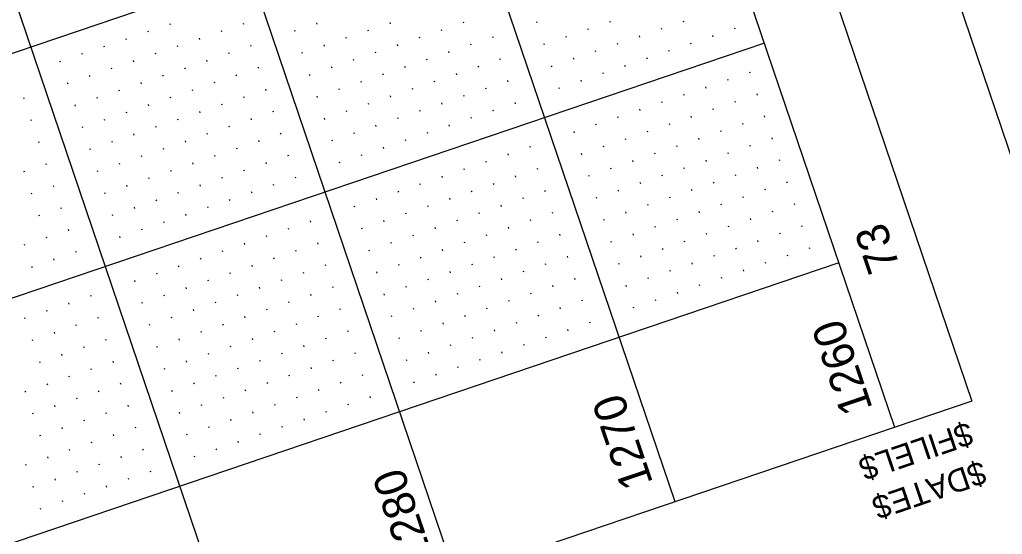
# Model space of a CAD drawing. Extents: x 2150800 to 2152547, y 141860 to 143950.
# Drawn here: x 2152172.8 to 2152384.7, y 142359.9 to 142470.9 of the extents above; entities that cross this region are included whole.
import ezdxf

# ---------------------------------------------------------------- set-up
doc = ezdxf.new("R2010")
doc.units = 0
for name, color, linetype in [('SHT_Plan_Profile_Sheet_Elev_Txt', 7, 'Continuous'), ('SHT_Plan_Profile_Sheet_Sta_Txt', 7, 'Continuous'), ('SHT_Plot_Shape_Half', 7, 'Continuous'), ('SHT_Plot_Stamp', 7, 'Continuous'), ('SHT_Profile_Grid_Major', 7, 'Continuous'), ('SHT_Profile_Grid_Minor', 7, 'Continuous'), ('SHT_Sheet_Border', 7, 'Continuous')]:
    doc.layers.add(name, color=color, linetype=linetype)

msp = doc.modelspace()

# ---------------------------------------------------------------- linework, layer by layer
at = {"layer": 'SHT_Plot_Shape_Half'}
msp.add_lwpolyline([(2151391.39, 141950.92), (2150845.24, 143560.8), (2151886.93, 143914.19), (2152433.08, 142304.31)], close=True, dxfattribs=at)
at = {"layer": 'SHT_Profile_Grid_Major'}
for p, q in [((2152314.16, 142366.92), (2151808.17, 143858.43)), ((2152266.81, 142350.86), (2151760.82, 143842.37)), ((2152219.46, 142334.8), (2151713.47, 143826.31)), ((2152317.33, 142513.2), (2151867.44, 142360.57)), ((2152333.4, 142465.85), (2151883.5, 142313.22))]:
    msp.add_line(p, q, dxfattribs=at)
at = {"layer": 'SHT_Profile_Grid_Minor'}
for p, q in [((2152205.34, 142469.79), (2152205.26, 142470.03)), ((2152221.15, 142469.88), (2152221.07, 142470.11)), ((2152236.96, 142469.96), (2152236.88, 142470.2)), ((2152252.78, 142470.04), (2152252.7, 142470.28)), ((2152263.85, 142468.52), (2152263.77, 142468.76)), ((2152268.59, 142470.13), (2152268.51, 142470.36)), ((2152284.4, 142470.21), (2152284.32, 142470.45)), ((2152295.47, 142468.69), (2152295.39, 142468.93)), ((2152300.21, 142470.3), (2152300.13, 142470.53)), ((2152311.29, 142468.77), (2152311.21, 142469.01)), ((2152316.02, 142470.38), (2152315.94, 142470.62)), ((2152327.1, 142468.86), (2152327.02, 142469.09)), ((2152195.87, 142466.58), (2152195.79, 142466.82)), ((2152200.61, 142468.19), (2152200.53, 142468.42)), ((2152211.68, 142466.66), (2152211.6, 142466.9)), ((2152216.42, 142468.27), (2152216.34, 142468.51)), ((2152232.23, 142468.35), (2152232.15, 142468.59)), ((2152243.31, 142466.83), (2152243.23, 142467.07)), ((2152248.04, 142468.44), (2152247.96, 142468.67)), ((2152259.12, 142466.92), (2152259.04, 142467.15)), ((2152274.93, 142467), (2152274.85, 142467.24)), ((2152290.74, 142467.08), (2152290.66, 142467.32)), ((2152306.55, 142467.17), (2152306.47, 142467.4)), ((2152322.36, 142467.25), (2152322.28, 142467.49)), ((2152191.14, 142464.97), (2152191.06, 142465.21)), ((2152206.95, 142465.06), (2152206.87, 142465.29)), ((2152222.76, 142465.14), (2152222.68, 142465.38)), ((2152238.57, 142465.22), (2152238.49, 142465.46)), ((2152254.38, 142465.31), (2152254.3, 142465.55)), ((2152270.19, 142465.39), (2152270.11, 142465.63)), ((2152286, 142465.48), (2152285.92, 142465.71)), ((2152301.82, 142465.56), (2152301.74, 142465.8)), ((2152317.63, 142465.64), (2152317.55, 142465.88)), ((2152186.4, 142463.37), (2152186.32, 142463.6)), ((2152202.21, 142463.45), (2152202.13, 142463.69)), ((2152218.03, 142463.53), (2152217.94, 142463.77)), ((2152233.84, 142463.62), (2152233.76, 142463.86)), ((2152249.65, 142463.7), (2152249.57, 142463.94)), ((2152260.72, 142462.18), (2152260.64, 142462.42)), ((2152265.46, 142463.79), (2152265.38, 142464.02)), ((2152276.53, 142462.26), (2152276.45, 142462.5)), ((2152292.35, 142462.35), (2152292.27, 142462.58)), ((2152297.08, 142463.95), (2152297, 142464.19)), ((2152308.16, 142462.43), (2152308.08, 142462.67)), ((2152312.89, 142464.04), (2152312.81, 142464.28)), ((2152181.67, 142461.76), (2152181.59, 142462)), ((2152192.74, 142460.24), (2152192.66, 142460.47)), ((2152197.48, 142461.84), (2152197.4, 142462.08)), ((2152208.56, 142460.32), (2152208.47, 142460.56)), ((2152213.29, 142461.93), (2152213.21, 142462.16)), ((2152224.37, 142460.41), (2152224.29, 142460.64)), ((2152240.18, 142460.49), (2152240.1, 142460.73)), ((2152244.91, 142462.1), (2152244.83, 142462.33)), ((2152255.99, 142460.57), (2152255.91, 142460.81)), ((2152271.8, 142460.66), (2152271.72, 142460.89)), ((2152287.61, 142460.74), (2152287.53, 142460.98)), ((2152303.42, 142460.83), (2152303.34, 142461.06)), ((2152188.01, 142458.63), (2152187.93, 142458.87)), ((2152203.82, 142458.72), (2152203.74, 142458.95)), ((2152219.63, 142458.8), (2152219.55, 142459.04)), ((2152235.44, 142458.88), (2152235.36, 142459.12)), ((2152251.25, 142458.97), (2152251.17, 142459.2)), ((2152267.06, 142459.05), (2152266.98, 142459.29)), ((2152298.69, 142459.22), (2152298.61, 142459.46)), ((2152330.31, 142459.39), (2152330.23, 142459.62)), ((2152183.27, 142457.03), (2152183.19, 142457.26)), ((2152199.09, 142457.11), (2152199, 142457.35)), ((2152214.9, 142457.19), (2152214.82, 142457.43)), ((2152246.52, 142457.36), (2152246.44, 142457.6)), ((2152257.59, 142455.84), (2152257.51, 142456.08)), ((2152262.33, 142457.45), (2152262.25, 142457.68)), ((2152273.41, 142455.92), (2152273.33, 142456.16)), ((2152278.14, 142457.53), (2152278.06, 142457.77)), ((2152289.22, 142456.01), (2152289.14, 142456.24)), ((2152293.95, 142457.61), (2152293.87, 142457.85)), ((2152320.84, 142456.17), (2152320.76, 142456.41)), ((2152325.57, 142457.78), (2152325.49, 142458.02)), ((2152173.8, 142453.81), (2152173.72, 142454.05)), ((2152189.62, 142453.9), (2152189.54, 142454.13)), ((2152194.35, 142455.5), (2152194.27, 142455.74)), ((2152205.43, 142453.98), (2152205.35, 142454.22)), ((2152210.16, 142455.59), (2152210.08, 142455.82)), ((2152221.24, 142454.06), (2152221.16, 142454.3)), ((2152225.97, 142455.67), (2152225.89, 142455.91)), ((2152237.05, 142454.15), (2152236.97, 142454.39)), ((2152241.78, 142455.75), (2152241.7, 142455.99)), ((2152252.86, 142454.23), (2152252.78, 142454.47)), ((2152268.67, 142454.32), (2152268.59, 142454.55)), ((2152316.1, 142454.57), (2152316.02, 142454.81)), ((2152331.92, 142454.65), (2152331.84, 142454.89)), ((2152184.88, 142452.29), (2152184.8, 142452.53)), ((2152200.69, 142452.37), (2152200.61, 142452.61)), ((2152216.5, 142452.46), (2152216.42, 142452.69)), ((2152248.13, 142452.63), (2152248.04, 142452.86)), ((2152263.94, 142452.71), (2152263.86, 142452.95)), ((2152279.75, 142452.79), (2152279.67, 142453.03)), ((2152311.37, 142452.96), (2152311.29, 142453.2)), ((2152327.18, 142453.05), (2152327.1, 142453.28)), ((2152195.96, 142450.77), (2152195.88, 142451)), ((2152211.77, 142450.85), (2152211.69, 142451.09)), ((2152227.58, 142450.94), (2152227.5, 142451.17)), ((2152243.39, 142451.02), (2152243.31, 142451.26)), ((2152254.47, 142449.5), (2152254.39, 142449.73)), ((2152259.2, 142451.1), (2152259.12, 142451.34)), ((2152270.28, 142449.58), (2152270.2, 142449.82)), ((2152275.01, 142451.19), (2152274.93, 142451.42)), ((2152301.9, 142449.75), (2152301.82, 142449.99)), ((2152306.63, 142451.36), (2152306.55, 142451.59)), ((2152317.71, 142449.83), (2152317.63, 142450.07)), ((2152322.45, 142451.44), (2152322.37, 142451.68)), ((2152333.52, 142449.92), (2152333.44, 142450.15)), ((2152175.41, 142449.08), (2152175.33, 142449.31)), ((2152186.49, 142447.56), (2152186.41, 142447.79)), ((2152191.22, 142449.16), (2152191.14, 142449.4)), ((2152202.3, 142447.64), (2152202.22, 142447.88)), ((2152207.03, 142449.25), (2152206.95, 142449.48)), ((2152218.11, 142447.72), (2152218.03, 142447.96)), ((2152222.84, 142449.33), (2152222.76, 142449.57)), ((2152238.66, 142449.41), (2152238.57, 142449.65)), ((2152249.73, 142447.89), (2152249.65, 142448.13)), ((2152265.54, 142447.98), (2152265.46, 142448.21)), ((2152297.16, 142448.14), (2152297.08, 142448.38)), ((2152312.98, 142448.23), (2152312.9, 142448.46)), ((2152328.79, 142448.31), (2152328.71, 142448.55)), ((2152197.56, 142446.03), (2152197.48, 142446.27)), ((2152213.37, 142446.12), (2152213.29, 142446.35)), ((2152229.19, 142446.2), (2152229.1, 142446.44)), ((2152245, 142446.28), (2152244.92, 142446.52)), ((2152260.81, 142446.37), (2152260.73, 142446.61)), ((2152292.43, 142446.54), (2152292.35, 142446.77)), ((2152308.24, 142446.62), (2152308.16, 142446.86)), ((2152324.05, 142446.7), (2152323.97, 142446.94)), ((2152177.02, 142444.34), (2152176.94, 142444.58)), ((2152192.83, 142444.43), (2152192.75, 142444.66)), ((2152208.64, 142444.51), (2152208.56, 142444.75)), ((2152224.45, 142444.59), (2152224.37, 142444.83)), ((2152240.26, 142444.68), (2152240.18, 142444.92)), ((2152251.34, 142443.16), (2152251.26, 142443.39)), ((2152256.07, 142444.76), (2152255.99, 142445)), ((2152282.96, 142443.32), (2152282.88, 142443.56)), ((2152298.77, 142443.41), (2152298.69, 142443.65)), ((2152303.51, 142445.01), (2152303.43, 142445.25)), ((2152314.58, 142443.49), (2152314.5, 142443.73)), ((2152319.32, 142445.1), (2152319.24, 142445.34)), ((2152330.39, 142443.58), (2152330.31, 142443.81)), ((2152335.13, 142445.18), (2152335.05, 142445.42)), ((2152188.09, 142442.82), (2152188.01, 142443.06)), ((2152199.17, 142441.3), (2152199.09, 142441.53)), ((2152203.9, 142442.9), (2152203.82, 142443.14)), ((2152214.98, 142441.38), (2152214.9, 142441.62)), ((2152219.72, 142442.99), (2152219.64, 142443.23)), ((2152230.79, 142441.47), (2152230.71, 142441.7)), ((2152246.6, 142441.55), (2152246.52, 142441.79)), ((2152278.23, 142441.72), (2152278.14, 142441.95)), ((2152294.04, 142441.8), (2152293.96, 142442.04)), ((2152309.85, 142441.89), (2152309.77, 142442.12)), ((2152325.66, 142441.97), (2152325.58, 142442.21)), ((2152178.62, 142439.61), (2152178.54, 142439.84)), ((2152194.43, 142439.69), (2152194.35, 142439.93)), ((2152210.25, 142439.78), (2152210.17, 142440.01)), ((2152226.06, 142439.86), (2152225.98, 142440.1)), ((2152241.87, 142439.94), (2152241.79, 142440.18)), ((2152273.49, 142440.11), (2152273.41, 142440.35)), ((2152305.11, 142440.28), (2152305.03, 142440.52)), ((2152320.92, 142440.36), (2152320.84, 142440.6)), ((2152332, 142438.84), (2152331.92, 142439.08)), ((2152336.73, 142440.45), (2152336.65, 142440.68)), ((2152173.89, 142438), (2152173.81, 142438.24)), ((2152189.7, 142438.09), (2152189.62, 142438.32)), ((2152205.51, 142438.17), (2152205.43, 142438.41)), ((2152221.32, 142438.25), (2152221.24, 142438.49)), ((2152232.4, 142436.73), (2152232.32, 142436.97)), ((2152264.02, 142436.9), (2152263.94, 142437.14)), ((2152268.76, 142438.51), (2152268.67, 142438.74)), ((2152279.83, 142436.98), (2152279.75, 142437.22)), ((2152284.57, 142438.59), (2152284.49, 142438.83)), ((2152295.64, 142437.07), (2152295.56, 142437.3)), ((2152300.38, 142438.67), (2152300.3, 142438.91)), ((2152311.45, 142437.15), (2152311.37, 142437.39)), ((2152316.19, 142438.76), (2152316.11, 142438.99)), ((2152327.26, 142437.24), (2152327.18, 142437.47)), ((2152180.23, 142434.87), (2152180.15, 142435.11)), ((2152196.04, 142434.96), (2152195.96, 142435.19)), ((2152200.78, 142436.56), (2152200.7, 142436.8)), ((2152211.85, 142435.04), (2152211.77, 142435.28)), ((2152216.59, 142436.65), (2152216.51, 142436.88)), ((2152227.66, 142435.12), (2152227.58, 142435.36)), ((2152259.29, 142435.29), (2152259.21, 142435.53)), ((2152275.1, 142435.38), (2152275.02, 142435.61)), ((2152306.72, 142435.54), (2152306.64, 142435.78)), ((2152322.53, 142435.63), (2152322.45, 142435.87)), ((2152338.34, 142435.71), (2152338.26, 142435.95)), ((2152175.49, 142433.27), (2152175.41, 142433.5)), ((2152191.31, 142433.35), (2152191.23, 142433.59)), ((2152207.12, 142433.43), (2152207.04, 142433.67)), ((2152222.93, 142433.52), (2152222.85, 142433.76)), ((2152254.55, 142433.69), (2152254.47, 142433.92)), ((2152270.36, 142433.77), (2152270.28, 142434.01)), ((2152286.17, 142433.85), (2152286.09, 142434.09)), ((2152301.98, 142433.94), (2152301.9, 142434.18)), ((2152317.8, 142434.02), (2152317.71, 142434.26)), ((2152328.87, 142432.5), (2152328.79, 142432.74)), ((2152333.61, 142434.11), (2152333.53, 142434.34)), ((2152202.38, 142431.83), (2152202.3, 142432.06)), ((2152218.19, 142431.91), (2152218.11, 142432.15)), ((2152245.08, 142430.47), (2152245, 142430.71)), ((2152249.82, 142432.08), (2152249.74, 142432.32)), ((2152260.89, 142430.56), (2152260.81, 142430.79)), ((2152265.63, 142432.16), (2152265.55, 142432.4)), ((2152276.7, 142430.64), (2152276.62, 142430.88)), ((2152281.44, 142432.25), (2152281.36, 142432.48)), ((2152297.25, 142432.33), (2152297.17, 142432.57)), ((2152308.33, 142430.81), (2152308.24, 142431.05)), ((2152313.06, 142432.42), (2152312.98, 142432.65)), ((2152324.14, 142430.89), (2152324.06, 142431.13)), ((2152339.95, 142430.98), (2152339.87, 142431.21)), ((2152177.1, 142428.53), (2152177.02, 142428.77)), ((2152181.84, 142430.14), (2152181.76, 142430.37)), ((2152192.91, 142428.62), (2152192.83, 142428.85)), ((2152197.65, 142430.22), (2152197.57, 142430.46)), ((2152208.72, 142428.7), (2152208.64, 142428.94)), ((2152213.46, 142430.31), (2152213.38, 142430.54)), ((2152256.16, 142428.95), (2152256.08, 142429.19)), ((2152271.97, 142429.04), (2152271.89, 142429.27)), ((2152287.78, 142429.12), (2152287.7, 142429.36)), ((2152303.59, 142429.2), (2152303.51, 142429.44)), ((2152319.4, 142429.29), (2152319.32, 142429.52)), ((2152335.21, 142429.37), (2152335.13, 142429.61)), ((2152203.99, 142427.09), (2152203.91, 142427.33)), ((2152235.61, 142427.26), (2152235.53, 142427.5)), ((2152251.42, 142427.35), (2152251.34, 142427.58)), ((2152267.23, 142427.43), (2152267.15, 142427.67)), ((2152283.04, 142427.51), (2152282.96, 142427.75)), ((2152298.86, 142427.6), (2152298.77, 142427.83)), ((2152314.67, 142427.68), (2152314.59, 142427.92)), ((2152325.74, 142426.16), (2152325.66, 142426.4)), ((2152330.48, 142427.77), (2152330.4, 142428)), ((2152341.55, 142426.24), (2152341.47, 142426.48)), ((2152183.44, 142425.4), (2152183.36, 142425.64)), ((2152199.25, 142425.49), (2152199.17, 142425.72)), ((2152226.14, 142424.05), (2152226.06, 142424.29)), ((2152230.88, 142425.65), (2152230.8, 142425.89)), ((2152246.69, 142425.74), (2152246.61, 142425.98)), ((2152257.76, 142424.22), (2152257.68, 142424.45)), ((2152262.5, 142425.82), (2152262.42, 142426.06)), ((2152273.57, 142424.3), (2152273.49, 142424.54)), ((2152278.31, 142425.91), (2152278.23, 142426.14)), ((2152289.39, 142424.38), (2152289.3, 142424.62)), ((2152305.2, 142424.47), (2152305.12, 142424.71)), ((2152309.93, 142426.07), (2152309.85, 142426.31)), ((2152321.01, 142424.55), (2152320.93, 142424.79)), ((2152336.82, 142424.64), (2152336.74, 142424.87)), ((2152173.97, 142422.19), (2152173.89, 142422.43)), ((2152178.71, 142423.8), (2152178.63, 142424.03)), ((2152194.52, 142423.88), (2152194.44, 142424.12)), ((2152221.41, 142422.44), (2152221.33, 142422.68)), ((2152237.22, 142422.53), (2152237.14, 142422.76)), ((2152253.03, 142422.61), (2152252.95, 142422.85)), ((2152268.84, 142422.69), (2152268.76, 142422.93)), ((2152284.65, 142422.78), (2152284.57, 142423.01)), ((2152300.46, 142422.86), (2152300.38, 142423.1)), ((2152316.27, 142422.95), (2152316.19, 142423.18)), ((2152332.08, 142423.03), (2152332, 142423.27)), ((2152185.05, 142420.67), (2152184.97, 142420.9)), ((2152216.67, 142420.84), (2152216.59, 142421.07)), ((2152232.48, 142420.92), (2152232.4, 142421.16)), ((2152248.29, 142421), (2152248.21, 142421.24)), ((2152264.1, 142421.09), (2152264.02, 142421.32)), ((2152279.92, 142421.17), (2152279.84, 142421.41)), ((2152311.54, 142421.34), (2152311.46, 142421.58)), ((2152322.61, 142419.82), (2152322.53, 142420.05)), ((2152327.35, 142421.42), (2152327.27, 142421.66)), ((2152338.43, 142419.9), (2152338.34, 142420.14)), ((2152343.16, 142421.51), (2152343.08, 142421.74)), ((2152180.31, 142419.06), (2152180.23, 142419.3)), ((2152211.94, 142419.23), (2152211.86, 142419.47)), ((2152223.01, 142417.71), (2152222.93, 142417.94)), ((2152227.75, 142419.31), (2152227.67, 142419.55)), ((2152238.82, 142417.79), (2152238.74, 142418.03)), ((2152254.63, 142417.88), (2152254.55, 142418.11)), ((2152259.37, 142419.48), (2152259.29, 142419.72)), ((2152270.45, 142417.96), (2152270.37, 142418.2)), ((2152275.18, 142419.57), (2152275.1, 142419.8)), ((2152286.26, 142418.04), (2152286.18, 142418.28)), ((2152290.99, 142419.65), (2152290.91, 142419.89)), ((2152302.07, 142418.13), (2152301.99, 142418.36)), ((2152306.8, 142419.73), (2152306.72, 142419.97)), ((2152317.88, 142418.21), (2152317.8, 142418.45)), ((2152333.69, 142418.3), (2152333.61, 142418.53)), ((2152175.58, 142417.46), (2152175.5, 142417.69)), ((2152202.47, 142416.02), (2152202.39, 142416.25)), ((2152207.2, 142417.62), (2152207.12, 142417.86)), ((2152218.28, 142416.1), (2152218.2, 142416.34)), ((2152234.09, 142416.18), (2152234.01, 142416.42)), ((2152249.9, 142416.27), (2152249.82, 142416.51)), ((2152265.71, 142416.35), (2152265.63, 142416.59)), ((2152281.52, 142416.44), (2152281.44, 142416.67)), ((2152313.14, 142416.6), (2152313.06, 142416.84)), ((2152328.96, 142416.69), (2152328.87, 142416.93)), ((2152197.73, 142414.41), (2152197.65, 142414.65)), ((2152213.54, 142414.49), (2152213.46, 142414.73)), ((2152229.35, 142414.58), (2152229.27, 142414.82)), ((2152260.98, 142414.75), (2152260.9, 142414.98)), ((2152276.79, 142414.83), (2152276.71, 142415.07)), ((2152292.6, 142414.91), (2152292.52, 142415.15)), ((2152308.41, 142415), (2152308.33, 142415.24)), ((2152319.49, 142413.48), (2152319.41, 142413.71)), ((2152324.22, 142415.08), (2152324.14, 142415.32)), ((2152208.81, 142412.89), (2152208.73, 142413.13)), ((2152219.88, 142411.37), (2152219.8, 142411.6)), ((2152224.62, 142412.97), (2152224.54, 142413.21)), ((2152235.69, 142411.45), (2152235.61, 142411.69)), ((2152240.43, 142413.06), (2152240.35, 142413.29)), ((2152251.51, 142411.53), (2152251.43, 142411.77)), ((2152256.24, 142413.14), (2152256.16, 142413.38)), ((2152267.32, 142411.62), (2152267.24, 142411.85)), ((2152272.05, 142413.22), (2152271.97, 142413.46)), ((2152283.13, 142411.7), (2152283.05, 142411.94)), ((2152287.86, 142413.31), (2152287.78, 142413.55)), ((2152303.67, 142413.39), (2152303.59, 142413.63)), ((2152314.75, 142411.87), (2152314.67, 142412.11)), ((2152183.53, 142409.59), (2152183.45, 142409.83)), ((2152188.26, 142411.2), (2152188.18, 142411.43)), ((2152199.34, 142409.68), (2152199.26, 142409.91)), ((2152204.07, 142411.28), (2152203.99, 142411.52)), ((2152215.15, 142409.76), (2152215.07, 142410)), ((2152230.96, 142409.84), (2152230.88, 142410.08)), ((2152262.58, 142410.01), (2152262.5, 142410.25)), ((2152278.39, 142410.1), (2152278.31, 142410.33)), ((2152294.2, 142410.18), (2152294.12, 142410.42)), ((2152310.02, 142410.26), (2152309.94, 142410.5)), ((2152178.79, 142407.99), (2152178.71, 142408.22)), ((2152210.41, 142408.15), (2152210.33, 142408.39)), ((2152226.22, 142408.24), (2152226.14, 142408.47)), ((2152242.04, 142408.32), (2152241.96, 142408.56)), ((2152257.85, 142408.41), (2152257.77, 142408.64)), ((2152273.66, 142408.49), (2152273.58, 142408.73)), ((2152289.47, 142408.57), (2152289.39, 142408.81)), ((2152305.28, 142408.66), (2152305.2, 142408.89)), ((2152174.06, 142406.38), (2152173.98, 142406.62)), ((2152189.87, 142406.46), (2152189.79, 142406.7)), ((2152200.94, 142404.94), (2152200.86, 142405.18)), ((2152205.68, 142406.55), (2152205.6, 142406.78)), ((2152216.75, 142405.02), (2152216.67, 142405.26)), ((2152221.49, 142406.63), (2152221.41, 142406.87)), ((2152232.57, 142405.11), (2152232.49, 142405.35)), ((2152237.3, 142406.72), (2152237.22, 142406.95)), ((2152253.11, 142406.8), (2152253.03, 142407.04)), ((2152264.19, 142405.28), (2152264.11, 142405.51)), ((2152268.92, 142406.88), (2152268.84, 142407.12)), ((2152280, 142405.36), (2152279.92, 142405.6)), ((2152284.73, 142406.97), (2152284.65, 142407.2)), ((2152295.81, 142405.44), (2152295.73, 142405.68)), ((2152180.4, 142403.25), (2152180.32, 142403.49)), ((2152185.13, 142404.86), (2152185.05, 142405.09)), ((2152212.02, 142403.42), (2152211.94, 142403.66)), ((2152227.83, 142403.5), (2152227.75, 142403.74)), ((2152243.64, 142403.59), (2152243.56, 142403.82)), ((2152259.45, 142403.67), (2152259.37, 142403.91)), ((2152275.26, 142403.75), (2152275.18, 142403.99)), ((2152291.08, 142403.84), (2152291, 142404.08)), ((2152175.66, 142401.64), (2152175.58, 142401.88)), ((2152191.47, 142401.73), (2152191.39, 142401.96)), ((2152207.28, 142401.81), (2152207.2, 142402.05)), ((2152223.1, 142401.9), (2152223.02, 142402.13)), ((2152238.91, 142401.98), (2152238.83, 142402.22)), ((2152254.72, 142402.06), (2152254.64, 142402.3)), ((2152270.53, 142402.15), (2152270.45, 142402.38)), ((2152286.34, 142402.23), (2152286.26, 142402.47)), ((2152186.74, 142400.12), (2152186.66, 142400.36)), ((2152202.55, 142400.21), (2152202.47, 142400.44)), ((2152213.63, 142398.68), (2152213.55, 142398.92)), ((2152218.36, 142400.29), (2152218.28, 142400.53)), ((2152229.44, 142398.77), (2152229.36, 142399)), ((2152234.17, 142400.37), (2152234.09, 142400.61)), ((2152245.25, 142398.85), (2152245.17, 142399.09)), ((2152261.06, 142398.94), (2152260.98, 142399.17)), ((2152265.79, 142400.54), (2152265.71, 142400.78)), ((2152276.87, 142399.02), (2152276.79, 142399.26)), ((2152281.61, 142400.63), (2152281.53, 142400.86)), ((2152177.27, 142396.91), (2152177.19, 142397.15)), ((2152182, 142398.52), (2152181.92, 142398.75)), ((2152193.08, 142396.99), (2152193, 142397.23)), ((2152208.89, 142397.08), (2152208.81, 142397.31)), ((2152224.7, 142397.16), (2152224.62, 142397.4)), ((2152240.51, 142397.25), (2152240.43, 142397.48)), ((2152256.32, 142397.33), (2152256.24, 142397.57)), ((2152272.14, 142397.41), (2152272.06, 142397.65)), ((2152188.35, 142395.39), (2152188.26, 142395.62)), ((2152204.16, 142395.47), (2152204.08, 142395.71)), ((2152219.97, 142395.55), (2152219.89, 142395.79)), ((2152235.78, 142395.64), (2152235.7, 142395.88)), ((2152267.4, 142395.81), (2152267.32, 142396.04)), ((2152183.61, 142393.78), (2152183.53, 142394.02)), ((2152194.69, 142392.26), (2152194.61, 142392.49)), ((2152210.5, 142392.34), (2152210.42, 142392.58)), ((2152215.23, 142393.95), (2152215.15, 142394.19)), ((2152226.31, 142392.43), (2152226.23, 142392.66)), ((2152231.04, 142394.03), (2152230.96, 142394.27)), ((2152242.12, 142392.51), (2152242.04, 142392.75)), ((2152246.85, 142394.12), (2152246.77, 142394.35)), ((2152257.93, 142392.59), (2152257.85, 142392.83)), ((2152262.67, 142394.2), (2152262.59, 142394.44)), ((2152174.14, 142390.57), (2152174.06, 142390.8)), ((2152178.88, 142392.17), (2152178.79, 142392.41)), ((2152189.95, 142390.65), (2152189.87, 142390.89)), ((2152205.76, 142390.74), (2152205.68, 142390.97)), ((2152221.57, 142390.82), (2152221.49, 142391.06)), ((2152237.38, 142390.9), (2152237.3, 142391.14)), ((2152185.22, 142389.05), (2152185.14, 142389.28)), ((2152216.84, 142389.21), (2152216.76, 142389.45)), ((2152232.65, 142389.3), (2152232.57, 142389.53)), ((2152248.46, 142389.38), (2152248.38, 142389.62)), ((2152180.48, 142387.44), (2152180.4, 142387.68)), ((2152191.56, 142385.92), (2152191.48, 142386.15)), ((2152196.29, 142387.52), (2152196.21, 142387.76)), ((2152207.37, 142386), (2152207.29, 142386.24)), ((2152212.1, 142387.61), (2152212.02, 142387.84)), ((2152223.18, 142386.08), (2152223.1, 142386.32)), ((2152227.91, 142387.69), (2152227.83, 142387.93)), ((2152238.99, 142386.17), (2152238.91, 142386.41)), ((2152243.73, 142387.78), (2152243.65, 142388.01)), ((2152175.75, 142385.83), (2152175.67, 142386.07)), ((2152186.82, 142384.31), (2152186.74, 142384.55)), ((2152218.45, 142384.48), (2152218.36, 142384.72)), ((2152234.26, 142384.56), (2152234.18, 142384.8)), ((2152182.09, 142382.7), (2152182.01, 142382.94)), ((2152197.9, 142382.79), (2152197.82, 142383.03)), ((2152213.71, 142382.87), (2152213.63, 142383.11)), ((2152229.52, 142382.96), (2152229.44, 142383.19)), ((2152177.35, 142381.1), (2152177.27, 142381.33)), ((2152188.43, 142379.58), (2152188.35, 142379.81)), ((2152193.16, 142381.18), (2152193.08, 142381.42)), ((2152208.98, 142381.27), (2152208.89, 142381.5)), ((2152220.05, 142379.74), (2152219.97, 142379.98)), ((2152224.79, 142381.35), (2152224.71, 142381.59)), ((2152183.69, 142377.97), (2152183.61, 142378.21)), ((2152199.51, 142378.05), (2152199.42, 142378.29)), ((2152215.32, 142378.14), (2152215.24, 142378.37)), ((2152178.96, 142376.36), (2152178.88, 142376.6)), ((2152194.77, 142376.45), (2152194.69, 142376.68)), ((2152210.58, 142376.53), (2152210.5, 142376.77)), ((2152174.22, 142374.76), (2152174.14, 142374.99)), ((2152185.3, 142373.23), (2152185.22, 142373.47)), ((2152190.04, 142374.84), (2152189.96, 142375.08)), ((2152201.11, 142373.32), (2152201.03, 142373.56)), ((2152180.57, 142371.63), (2152180.49, 142371.86)), ((2152196.38, 142371.71), (2152196.3, 142371.95)), ((2152175.83, 142370.02), (2152175.75, 142370.26)), ((2152191.64, 142370.11), (2152191.56, 142370.34)), ((2152182.17, 142366.89), (2152182.09, 142367.13)), ((2152186.91, 142368.5), (2152186.83, 142368.74)), ((2152177.44, 142365.29), (2152177.36, 142365.52))]:
    msp.add_line(p, q, dxfattribs=at)
at = {"layer": 'SHT_Sheet_Border'}
for p, q in [((2152361.51, 142382.99), (2151939.85, 143625.91)), ((2152349.46, 142418.5), (2151875.97, 142257.87))]:
    msp.add_line(p, q, dxfattribs=at)
msp.add_lwpolyline([(2151383.74, 142051.28), (2150877.75, 143542.79), (2151872.09, 143880.12), (2152378.08, 142388.61)], close=True, dxfattribs=at)

# ---------------------------------------------------------------- texts
at = {"layer": 'SHT_Plan_Profile_Sheet_Elev_Txt'}
for s, p in [('1260', (2152356.79, 142387.08)), ('1270', (2152309.44, 142371.02)), ('1280', (2152262.09, 142354.95))]:
    msp.add_text(s, height=7, rotation=108.7393, dxfattribs=at).set_placement(p)
at = {"layer": 'SHT_Plan_Profile_Sheet_Sta_Txt'}
msp.add_text('73', height=7, rotation=108.7393, dxfattribs=at).set_placement((2152362.67, 142417.69))
at = {"layer": 'SHT_Plot_Stamp'}
for s, p in [('$FILEL$', (2152377.31, 142384.26)), ('$DATE$', (2152380.16, 142375.86))]:
    msp.add_text(s, height=5, rotation=198.7393, dxfattribs=at).set_placement(p)

doc.saveas('drawing.dxf')
